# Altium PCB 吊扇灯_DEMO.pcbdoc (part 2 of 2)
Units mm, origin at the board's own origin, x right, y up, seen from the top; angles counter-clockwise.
Board outline 117.71 x 71.75 mm, 2 copper layers (Top Layer, Bottom Layer); 71 components, 50 nets, 203 pads, 259 vias.
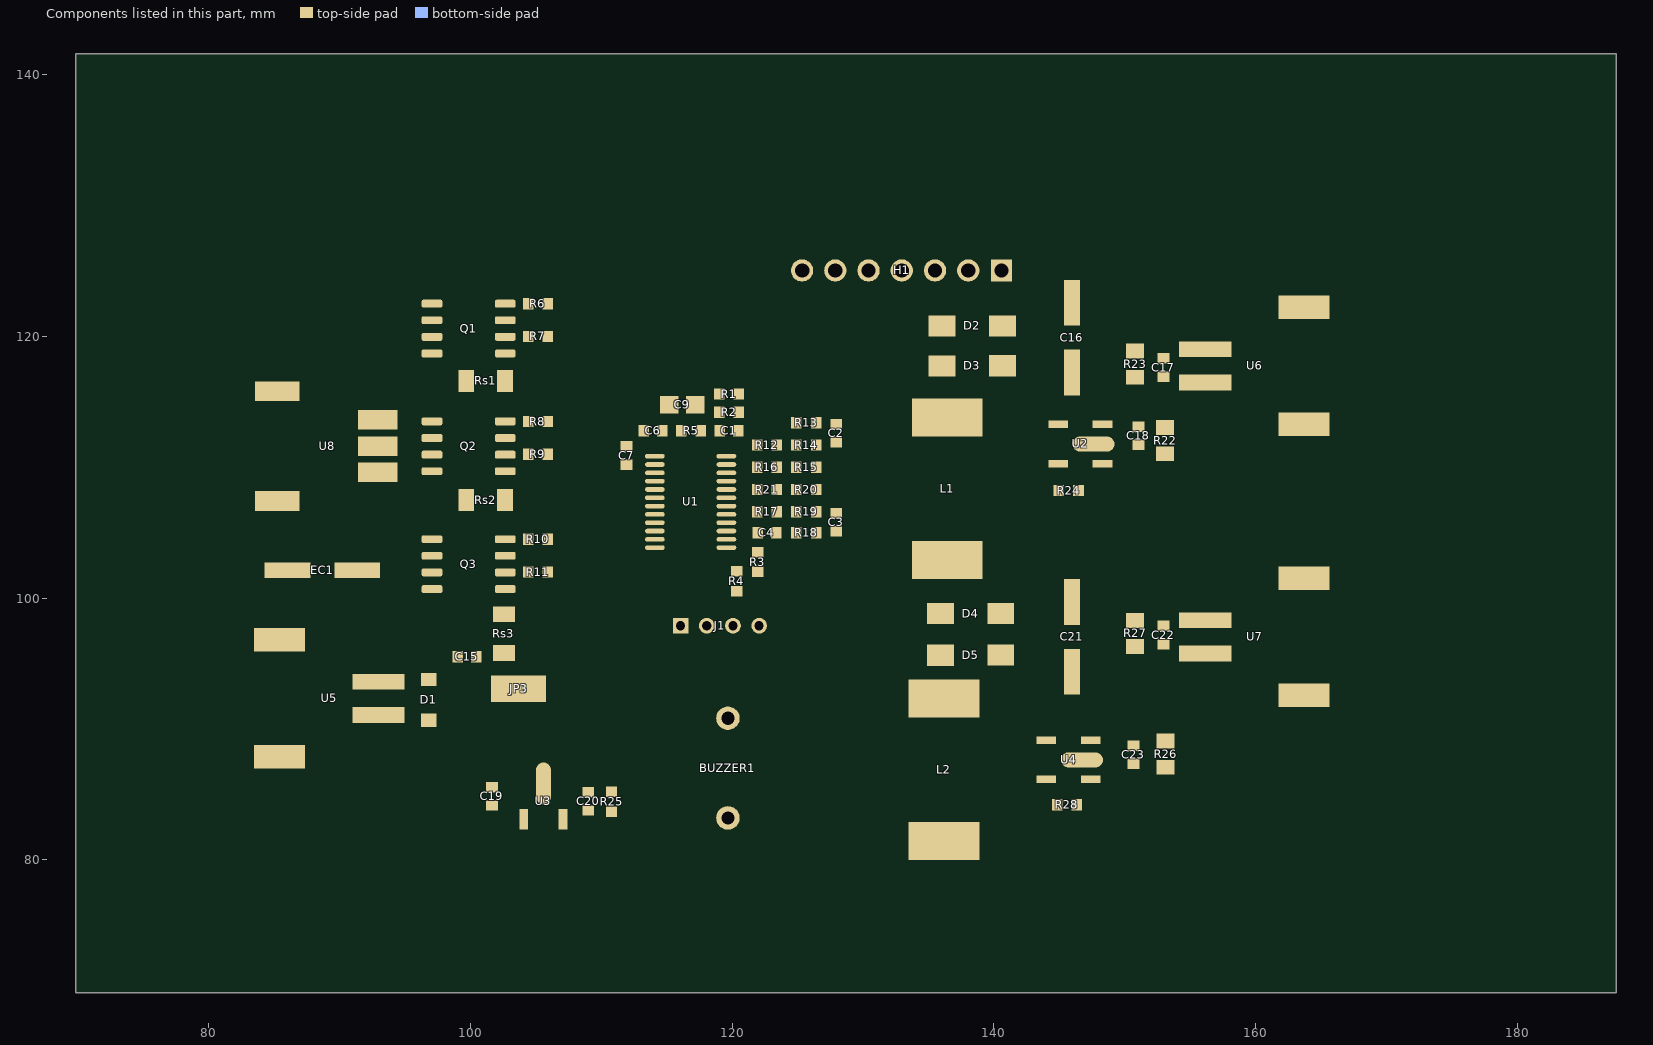
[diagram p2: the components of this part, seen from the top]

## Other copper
Top Layer:
  region net IBUS+: 98.37,117.401 98.77,117.801 99.97,117.801 100.27,117.501 100.27,101.801 101.07,101.001 103.77,101.001 104.07,100.701 104.07,98.001 103.97,97.901 100.27,97.901 100.17,98.001 100.17,98.901 98.37,100.701
  region net IS1+: 101.77,118.901 101.97,119.101 103.37,119.101 103.57,118.901 103.57,115.701 103.37,115.501 102.27,115.501 102.07,115.701 102.07,116.201 102.07,118.201 101.77,118.501
  region net IS1+: 101.77,118.901 101.97,119.101 103.37,119.101 103.57,118.901 103.57,115.701 103.37,115.501 102.27,115.501 102.07,115.701 102.07,116.201 102.07,118.201 101.77,118.501
  region net IS2+: 101.77,109.901 101.97,110.101 103.37,110.101 103.57,109.901 103.57,106.701 103.37,106.501 102.27,106.501 102.07,106.701 102.07,107.201 102.07,109.201 101.77,109.501
  region net 24V: 104.07,103.701 104.17,103.601 104.17,102.901 104.07,102.801 101.67,102.801 101.57,102.701 101.57,102.001 101.37,101.801 100.77,101.801 100.57,102.001 100.57,104.401 100.77,104.601 101.37,104.601 101.57,104.401 101.57,103.801 101.67,103.701
  region net 24V: 104.07,121.701 104.17,121.601 104.17,120.901 104.07,120.801 101.67,120.801 101.57,120.701 101.57,120.001 101.37,119.801 100.77,119.801 100.57,120.001 100.57,122.401 100.77,122.601 101.37,122.601 101.57,122.401 101.57,121.801 101.67,121.701
  region net 24V: 104.07,112.701 104.17,112.601 104.17,111.901 104.07,111.801 101.67,111.801 101.57,111.701 101.57,111.001 101.37,110.801 100.77,110.801 100.57,111.001 100.57,113.401 100.77,113.601 101.37,113.601 101.57,113.401 101.57,112.801 101.67,112.701
  region net +5V: 118.19,83.444 118.916,83.944 119.005,83.949 119.085,83.963 119.16,83.983 119.232,84.007 119.378,84.059 119.458,84.082 119.546,84.099 118.82,82.961 118.804,83.006 118.783,83.051 118.758,83.095 118.728,83.138 118.656,83.22 118.573,83.293 118.481,83.355 118.433,83.381 118.385,83.403 118.335,83.42 118.286,83.433 118.238,83.441
  region net +5V: 120.91,83.36 120.91,83.06 120.841,83.057 120.781,83.048 120.73,83.034 120.686,83.015 120.648,82.991 120.615,82.963 120.585,82.932 120.558,82.896 120.506,82.817 120.448,82.728 120.376,82.633 120.332,82.584 120.28,82.535 120.28,83.885 120.332,83.836 120.376,83.787 120.448,83.692 120.506,83.604 120.558,83.524 120.585,83.489 120.615,83.457 120.648,83.429 120.686,83.405 120.73,83.386 120.781,83.372 120.841,83.363
  region net BEE: 119.812,89.605 119.558,89.605 119.555,89.677 119.545,89.738 119.531,89.791 119.511,89.835 119.486,89.872 119.457,89.905 119.423,89.933 119.387,89.959 119.211,90.064 119.162,90.097 119.112,90.136 119.061,90.182 119.01,90.235 120.36,90.235 120.308,90.182 120.258,90.136 120.207,90.097 120.159,90.064 119.983,89.959 119.946,89.933 119.913,89.905 119.884,89.872 119.859,89.835 119.839,89.791 119.824,89.738 119.815,89.677
  region net BEE: 118.46,90.704 118.46,90.958 118.531,90.961 118.593,90.97 118.645,90.985 118.689,91.005 118.727,91.029 118.759,91.059 118.787,91.092 118.813,91.129 118.918,91.304 118.951,91.353 118.99,91.403 119.036,91.454 119.09,91.506 119.09,90.156 119.036,90.207 118.99,90.258 118.951,90.308 118.918,90.357 118.813,90.532 118.787,90.569 118.759,90.602 118.727,90.632 118.689,90.656 118.645,90.676 118.593,90.691 118.531,90.7
  region net AD_UDC: 118.755,112.245 118.564,112.337 ccw(c118.139,112.655) 118.67,112.655 119.073,112.351 ccw(c119.073,111.821)
  region net AD_UDC: 118.87,113.551 119.07,113.551 ccw(c119.445,113.551) 119.22,113.251 118.72,113.251 ccw(c118.495,113.551)
  region net IS1-: 127.22,113.306 127.22,113.506 ccw(c127.22,113.881) 127.52,113.656 127.52,113.156 ccw(c127.22,112.931)
  region net IS1-: 128.526,112.992 128.434,112.8 ccw(c128.116,112.376) 128.116,112.906 128.42,113.31 ccw(c128.95,113.31)
  region net IS1+: 127.22,111.706 127.22,111.906 ccw(c127.22,112.281) 127.52,112.056 127.52,111.556 ccw(c127.22,111.331)
  region net IS1+: 128.434,112.412 128.526,112.221 ccw(c128.95,111.903) 128.42,111.903 128.116,112.306 ccw(c128.116,112.837)
  region net IS2-: 127.22,104.906 127.22,105.106 ccw(c127.22,105.481) 127.52,105.256 127.52,104.756 ccw(c127.22,104.531)
  region net IS2-: 128.434,105.612 128.526,105.421 ccw(c128.95,105.103) 128.42,105.103 128.116,105.506 ccw(c128.116,106.037)
  region net IS2+: 127.22,106.506 127.22,106.706 ccw(c127.22,107.081) 127.52,106.856 127.52,106.356 ccw(c127.22,106.131)
  region net IS2+: 128.526,106.192 128.434,106 ccw(c128.116,105.576) 128.116,106.106 128.42,106.51 ccw(c128.95,106.51)
  region net ICOMP_P: 121.412,105.318 121.353,105.659 ccw(c126.615,110.921) 121.57,105.451 121.57,105.051 ccw(c120.97,104.876)
  region net ICOMP_P: 121.97,104.251 121.77,104.251 ccw(c121.395,104.251) 121.62,104.551 122.12,104.551 ccw(c122.345,104.251)
  region net $1N32: 114.945,111.901 114.595,111.901 ccw(c114.078,111.901) 114.332,112.351 115.07,112.351 ccw(c115.817,111.901)
  region net $1N32: 115.595,112.976 115.595,112.626 ccw(c115.595,111.97) 115.07,112.364 115.07,113.239 ccw(c115.595,113.633)
  region net 5VA: 111.07,109.951 111.07,110.251 ccw(c111.07,110.752) 111.488,110.476 111.488,109.796 ccw(c111.07,109.31)
  region net 5VA: 112.838,110.366 112.838,110.066 ccw(c112.838,109.504) 112.388,109.841 112.388,110.591 ccw(c112.838,110.929)
  region net 24V: 117.92,115.776 118.212,115.219 ccw(c119.485,114.265) 117.894,114.265 116.965,115.457 ccw(c116.965,117.048)
  region net 24V: 117.87,113.207 117.27,113.207 ccw(c116.145,113.207) 116.82,114.107 117.894,114.107 ccw(c134.758,113.207)
  region net 24V: 102.851,85.811 102.851,85.311 ccw(c102.851,83.361) 102.101,85.161 102.101,85.961 ccw(c102.851,87.761)
  region net 24V: 101.979,86.244 102.383,85.94 ccw(c103.316,85.161) 102.101,85.161 101.201,85.961 ccw(c101.201,87.177)
  region net +5V: 108.688,83.098 108.285,83.402 ccw(c107.351,84.18) 108.567,84.18 109.467,83.38 ccw(c109.467,82.165)
  region net +5V: 110.217,84.03 110.217,83.53 ccw(c110.217,81.58) 109.467,83.38 109.467,84.18 ccw(c110.217,85.98)
  region net GND: 122.753,97.43 122.541,97.218 122.483,97.267 122.426,97.297 122.369,97.311 122.312,97.315 122.185,97.306 122.113,97.301 122.032,97.303 122.669,97.939 122.67,97.859 122.665,97.786 122.656,97.66 122.66,97.602 122.675,97.545 122.704,97.488
  region net GND: 121.598,97.218 121.386,97.43 121.435,97.488 121.465,97.545 121.48,97.602 121.483,97.66 121.474,97.786 121.47,97.859 121.471,97.939 122.107,97.303 122.027,97.301 121.955,97.306 121.828,97.315 121.77,97.311 121.714,97.297 121.657,97.267
  region net GND: 122.541,98.585 122.753,98.373 122.704,98.314 122.675,98.258 122.66,98.201 122.656,98.143 122.665,98.016 122.67,97.944 122.669,97.864 122.032,98.5 122.113,98.501 122.185,98.497 122.312,98.488 122.369,98.492 122.426,98.506 122.483,98.536
  region net GND: 121.386,98.373 121.598,98.585 121.657,98.536 121.714,98.506 121.77,98.492 121.828,98.488 121.955,98.497 122.027,98.501 122.107,98.5 121.471,97.864 121.47,97.944 121.474,98.016 121.483,98.143 121.48,98.201 121.465,98.258 121.435,98.314
  region net SWDCLK: 119.421,98.408 119.563,98.55 119.597,98.519 119.629,98.495 119.66,98.477 119.69,98.465 119.719,98.459 119.748,98.456 119.806,98.461 119.937,98.489 120.016,98.499 120.107,98.5 119.471,97.864 119.472,97.955 119.483,98.034 119.51,98.165 119.515,98.223 119.513,98.252 119.506,98.281 119.494,98.311 119.477,98.342 119.453,98.374
  region net SWDIO: 118.577,98.55 118.718,98.408 118.687,98.374 118.663,98.342 118.645,98.311 118.634,98.281 118.627,98.252 118.625,98.223 118.629,98.165 118.657,98.034 118.668,97.955 118.669,97.864 118.032,98.5 118.124,98.499 118.202,98.489 118.333,98.461 118.392,98.456 118.421,98.459 118.45,98.465 118.48,98.477 118.51,98.495 118.543,98.519
  region net 5VA: 116.617,98.66 116.829,98.448 ccw(c117.465,97.971) 116.67,97.971 116.139,98.501 ccw(c116.139,99.297)
  region net $1N1115: 104.22,120.271 104.22,119.671 103.32,119.671 103.32,120.271
  region net $1N1124: 104.22,122.811 104.22,122.211 103.32,122.211 103.32,122.811
  region net $1N1118: 104.22,111.271 104.22,110.671 103.32,110.671 103.32,111.271
  region net $1N1122: 104.22,113.811 104.22,113.211 103.32,113.211 103.32,113.811
  region net AD_UDC: 120.173,115.063 120.014,115.187 ccw(c119.59,115.505) 120.12,115.505 120.491,115.169 ccw(c120.491,114.639)
  region net 24V: 118.17,115.301 118.17,115.901 ccw(c118.17,116.712) 118.613,116.033 118.613,115.169 ccw(c118.17,114.491)
  region net 24V: 118.72,116.933 119.32,116.933 ccw(c123.425,116.933) 119.42,116.033 118.613,116.033 ccw(c114.867,116.933)
  region net AD_UDC: 119.366,114.739 119.526,114.616 ccw(c119.95,114.298) 119.42,114.298 119.048,114.633 ccw(c119.048,115.164)
  region net AD_UDC: 119.07,113.469 118.87,113.469 ccw(c118.495,113.469) 118.72,113.769 119.22,113.769 ccw(c119.445,113.469)
  region net IBUS+: 122.784,102.142 122.784,101.888 ccw(c122.784,101.412) 122.403,101.698 122.403,102.333 ccw(c122.784,102.618)
  region net ICOMP_P: 121.77,104.225 121.97,104.225 ccw(c122.345,104.225) 122.12,103.925 121.62,103.925 ccw(c121.395,104.225)
  region net LED2_PWM: 119.832,102.498 120.049,102.564 ccw(c120.367,102.988) 120.367,102.458 119.938,102.18 ccw(c119.407,102.18)
  region net LED2_PWM: 120.937,101.668 120.728,101.517 ccw(c120.324,100.978) 120.324,101.652 120.802,102.072 ccw(c121.475,102.072)
  region net $1N32: 115.188,112.626 115.188,112.976 ccw(c115.188,113.641) 115.713,113.233 115.713,112.369 ccw(c115.188,111.962)
  region net 24V: 117.27,114.133 117.87,114.133 ccw(c120.534,114.133) 118.026,113.233 117.22,113.233 ccw(c109.125,114.133)
  region net 24V: 117.464,111.977 116.981,112.131 ccw(c116.027,112.847) 117.22,112.847 118.026,112.369 ccw(c118.843,110.598)
  region net $1N1124: 103.113,122.211 103.113,122.811 ccw(c103.113,126.192) 104.013,122.933 104.013,122.069 ccw(c103.113,119.288)
  region net HOU: 106.851,122.676 106.851,122.326 ccw(c106.851,121.662) 106.326,122.069 106.326,122.933 ccw(c106.851,123.341)
  region net $1N1115: 103.113,119.671 103.113,120.271 ccw(c103.113,122.852) 104.013,120.433 104.013,119.569 ccw(c103.113,115.65)
  region net LOU: 106.851,120.176 106.851,119.826 ccw(c106.851,119.162) 106.326,119.569 106.326,120.433 ccw(c106.851,120.841)
  region net $1N1122: 103.113,113.211 103.113,113.811 ccw(c103.113,117.192) 104.013,113.933 104.013,113.069 ccw(c103.113,110.288)
  region net HOV: 106.851,113.676 106.851,113.326 ccw(c106.851,112.662) 106.326,113.069 106.326,113.933 ccw(c106.851,114.341)
  region net $1N1118: 103.113,110.671 103.113,111.271 ccw(c103.113,113.852) 104.013,111.433 104.013,110.569 ccw(c103.113,106.65)
  region net LOV: 106.512,110.707 106.34,110.384 ccw(c105.783,109.641) 105.783,110.569 106.326,111.264 ccw(c107.254,111.264)
  region net $1N1123: 103.113,104.211 103.113,104.811 ccw(c103.113,108.192) 104.013,104.933 104.013,104.069 ccw(c103.113,101.288)
  region net HOW: 106.851,104.676 106.851,104.326 ccw(c106.851,103.662) 106.326,104.069 106.326,104.933 ccw(c106.851,105.341)
  region net $1N1121: 103.113,101.671 103.113,102.271 ccw(c103.113,104.852) 104.013,102.433 104.013,101.569 ccw(c103.113,97.65)
  region net LOW: 106.851,102.176 106.851,101.826 ccw(c106.851,101.162) 106.326,101.569 106.326,102.433 ccw(c106.851,102.841)
  region net OP2-: 123.073,111.168 122.914,111.292 ccw(c122.49,111.61) 123.02,111.61 123.391,111.274 ccw(c123.391,110.744)
  region net OP2-: 123.618,112.296 123.997,112.392 ccw(c124.559,111.83) 123.826,112.138 123.352,112.138 ccw(c123.177,112.738)
  region net IS1-: 127.126,113.506 127.126,113.306 ccw(c127.126,112.931) 126.826,113.156 126.826,113.656 ccw(c127.126,113.881)
  region net OP2-: 124.473,112.868 124.407,113.085 ccw(c123.983,113.403) 124.513,113.403 124.791,112.974 ccw(c124.791,112.444)
  region net IS1+: 127.126,111.906 127.126,111.706 ccw(c127.126,111.331) 126.826,111.556 126.826,112.056 ccw(c127.126,112.281)
  region net OP2+: 124.97,110.974 124.77,110.974 ccw(c124.395,110.974) 124.62,111.274 125.12,111.274 ccw(c125.345,110.974)
  region net OP2+: 124.77,110.738 124.97,110.738 ccw(c125.345,110.738) 125.12,110.438 124.62,110.438 ccw(c124.395,110.738)
  region net OP2+: 121.516,109.511 121.407,109.685 ccw(c120.983,110.003) 121.513,110.003 121.791,109.574 ccw(c121.791,108.945)
  region net OP2+: 122.266,110.544 122.426,110.421 ccw(c122.85,110.103) 122.32,110.103 121.948,110.438 ccw(c121.948,110.969)
  region net 5VA: 123.62,109.156 123.32,109.156 ccw(c122.819,109.156) 123.095,109.574 123.826,109.574 ccw(c124.146,109.156)
  region net OP1-: 122.794,106.906 122.794,107.106 ccw(c123.02,107.448) 123.02,107.038 123.02,106.756 ccw(c122.794,106.661)
  region net OP1-: 123.932,106.185 123.766,106.068 ccw(c123.448,105.644) 123.448,106.174 123.826,106.503 ccw(c124.357,106.503)
  region net IS2-: 127.126,105.106 127.126,104.906 ccw(c127.126,104.531) 126.826,104.756 126.826,105.256 ccw(c127.126,105.481)
  region net OP1-: 124.407,105.428 124.573,105.544 ccw(c124.891,105.969) 124.891,105.438 124.513,105.109 ccw(c123.983,105.109)
  region net IS2+: 127.126,106.706 127.126,106.506 ccw(c127.126,106.131) 126.826,106.356 126.826,106.856 ccw(c127.126,107.081)
  region net OP1+: 124.77,107.338 124.97,107.338 ccw(c125.345,107.338) 125.12,107.038 124.62,107.038 ccw(c124.395,107.338)
  region net OP1+: 124.97,107.574 124.77,107.574 ccw(c124.395,107.574) 124.62,107.874 125.12,107.874 ccw(c125.345,107.574)
  region net OP1+: 121.407,108.628 121.473,108.844 ccw(c121.791,109.269) 121.791,108.738 121.513,108.309 ccw(c120.983,108.309)
  region net OP1+: 122.426,107.892 122.266,107.768 ccw(c121.948,107.344) 121.948,107.874 122.32,108.21 ccw(c122.85,108.21)
  region net 5VA: 123.32,109.156 123.62,109.156 ccw(c124.146,109.156) 123.826,108.738 123.095,108.738 ccw(c122.819,109.156)
  region net LED_PWM: 144.182,108.102 144.182,108.356 ccw(c144.182,108.833) 144.563,108.547 144.563,107.912 ccw(c144.182,107.626)
  region net $1N4328: 146.355,109.042 146.609,109.042 ccw(c147.085,109.042) 146.799,108.661 146.164,108.661 ccw(c145.879,109.042)
  region net +5V: 109.613,83.53 109.613,84.03 ccw(c109.613,88.268) 110.363,84.097 110.363,83.291 ccw(c109.613,82.237)
  region net +5V: 111.977,83.944 111.977,83.444 ccw(c111.977,81.532) 111.227,83.291 111.227,84.097 ccw(c111.977,85.856)
  region net BEE: 111.608,85.328 111.608,85.074 ccw(c111.608,84.598) 111.227,84.883 111.227,85.518 ccw(c111.608,85.804)
  region net LED2_PWM: 144.055,84.099 144.055,84.353 ccw(c144.055,84.83) 144.436,84.544 144.436,83.909 ccw(c144.055,83.623)
  region net $2N531: 145.808,84.585 145.959,84.793 ccw(c146.363,85.332) 146.363,84.658 145.943,84.181 ccw(c145.269,84.181)
  region net IBUS+: 100.595,116.701 100.595,116.501 ccw(c100.595,116.126) 100.295,116.351 100.295,116.851 ccw(c100.595,117.076)
  region net IS1+: 101.87,116.501 101.87,116.701 ccw(c101.87,116.879) 102.045,116.851 102.045,116.351 ccw(c101.87,116.324)
  region net IS2+: 101.745,107.401 101.745,107.601 ccw(c101.745,107.976) 102.045,107.751 102.045,107.251 ccw(c101.745,107.026)
  region net IBUS+: 103.801,98.907 103.801,98.653 ccw(c103.801,98.177) 103.42,98.463 103.42,99.098 ccw(c103.801,99.383)
  region net BEE: 114.227,103.308 113.973,103.308 113.97,103.447 113.963,103.512 113.949,103.57 113.926,103.618 113.911,103.639 113.893,103.656 113.871,103.67 113.845,103.68 113.816,103.686 113.782,103.689 114.417,103.689 114.384,103.686 114.355,103.68 114.329,103.67 114.307,103.656 114.289,103.639 114.273,103.618 114.251,103.57 114.237,103.512 114.23,103.447
  region net OUT1: 115.056,104.628 115.056,104.374 114.986,104.372 114.919,104.366 114.803,104.349 114.675,104.324 114.675,104.679 114.803,104.654 114.919,104.636 114.986,104.631
  region net LOW: 113,104.961 113,105.311 113.525,105.314 113.525,104.959
  region net HOW: 113,105.596 113,105.946 113.525,105.949 113.525,105.594
  region net LOV: 113,106.231 113,106.581 113.525,106.584 113.525,106.229
  region net HOV: 113,106.866 113,107.216 113.525,107.219 113.525,106.864
  region net LOU: 113,107.501 113,107.851 113.525,107.854 113.525,107.499
  region net HOU: 113,108.136 113,108.486 113.525,108.489 113.525,108.134
  region net $1N32: 115.17,109.756 115.17,109.406 114.675,109.404 114.675,109.759
  region net 5VA: 113.075,110.066 113.075,110.366 113.237,110.371 113.375,110.38 113.525,110.394 113.525,110.039 113.375,110.053 113.237,110.062
  region net OP2O: 120.445,110.951 120.445,110.751 120.39,110.748 120.338,110.739 120.248,110.713 120.181,110.686 120.145,110.674 120.145,111.029 120.181,111.017 120.248,110.99 120.338,110.964 120.39,110.955
  region net OP2-: 120.445,110.316 120.445,110.116 120.39,110.113 120.338,110.104 120.248,110.078 120.181,110.051 120.145,110.039 120.145,110.394 120.181,110.382 120.248,110.355 120.338,110.329 120.39,110.32
  region net OP2+: 120.445,109.681 120.445,109.481 120.39,109.478 120.338,109.469 120.248,109.443 120.181,109.416 120.145,109.404 120.145,109.759 120.181,109.747 120.248,109.72 120.338,109.694 120.39,109.685
  region net OP1+: 120.445,109.046 120.445,108.846 120.39,108.843 120.338,108.834 120.248,108.808 120.181,108.781 120.145,108.769 120.145,109.124 120.181,109.112 120.248,109.085 120.338,109.059 120.39,109.05
  region net OP1-: 120.445,108.411 120.445,108.211 120.393,108.208 120.354,108.199 120.322,108.187 120.295,108.173 120.267,108.158 120.235,108.146 120.196,108.137 120.145,108.134 120.145,108.489 120.196,108.486 120.235,108.477 120.267,108.465 120.295,108.45 120.322,108.436 120.354,108.424 120.393,108.415
  region net OP1O: 120.4,107.776 120.4,107.576 120.356,107.573 120.322,107.564 120.296,107.552 120.272,107.538 120.249,107.523 120.222,107.511 120.188,107.502 120.145,107.499 120.145,107.854 120.188,107.851 120.222,107.842 120.249,107.83 120.272,107.815 120.296,107.801 120.322,107.789 120.356,107.78
  region net AD_UDC: 118.695,106.941 118.695,107.141 118.75,107.145 118.802,107.154 118.892,107.18 118.959,107.207 118.995,107.219 118.995,106.864 118.959,106.876 118.892,106.902 118.802,106.929 118.75,106.938
  region net ICOMP_P: 120.445,106.506 120.445,106.306 120.39,106.303 120.338,106.294 120.248,106.267 120.181,106.241 120.145,106.229 120.145,106.584 120.181,106.572 120.248,106.545 120.338,106.519 120.39,106.51
  region net LED_PWM: 120.416,105.898 120.416,105.644 120.366,105.642 120.32,105.636 120.239,105.619 120.179,105.602 120.145,105.594 120.145,105.949 120.179,105.941 120.239,105.924 120.32,105.906 120.366,105.901
  region net SWDIO: 118.695,105.036 118.695,105.236 118.75,105.24 118.802,105.249 118.892,105.275 118.959,105.302 118.995,105.314 118.995,104.959 118.959,104.971 118.892,104.997 118.802,105.024 118.75,105.033
  region net SWDCLK: 118.695,104.401 118.695,104.601 118.75,104.605 118.802,104.614 118.892,104.64 118.959,104.667 118.995,104.679 118.995,104.324 118.959,104.336 118.892,104.362 118.802,104.389 118.75,104.398
  region net LED2_PWM: 119.67,103.389 119.47,103.389 119.467,103.499 119.462,103.549 119.451,103.595 119.433,103.633 119.407,103.663 119.389,103.674 119.369,103.682 119.32,103.689 119.82,103.689 119.77,103.682 119.75,103.674 119.733,103.663 119.706,103.633 119.689,103.595 119.678,103.549 119.672,103.499
  region net $1N4328: 145.796,110.111 145.684,109.864 ccw(c145.28,109.325) 145.28,109.998 145.661,110.515 ccw(c146.335,110.515)
  region net +5V: 108.174,83.374 108.174,82.874 ccw(c108.174,81.937) 107.424,82.499 107.424,83.749 ccw(c108.174,84.312)
  region net $2N531: 144.907,85.845 144.659,85.734 ccw(c144.255,85.195) 144.255,85.868 144.772,86.249 ccw(c145.446,86.249)
  region net OUT1: 134.761,124.155 134.62,124.297 134.644,124.327 134.662,124.364 134.676,124.407 134.685,124.454 134.693,124.56 134.689,124.675 134.669,124.907 134.661,125.011 134.661,125.097 135.562,124.196 135.475,124.196 135.372,124.204 135.14,124.225 135.024,124.228 134.919,124.22 134.871,124.211 134.829,124.198 134.792,124.179
  region net +5V: 138.199,124.181 137.899,124.181 137.895,124.213 137.883,124.241 137.864,124.265 137.84,124.286 137.81,124.304 137.777,124.32 137.701,124.349 137.619,124.374 137.539,124.402 137.467,124.437 137.437,124.458 137.412,124.482 138.686,124.482 138.661,124.458 138.631,124.437 138.559,124.402 138.479,124.374 138.397,124.349 138.321,124.32 138.288,124.304 138.258,124.286 138.234,124.265 138.215,124.241 138.203,124.213
  region net 24V: 103.888,85.311 103.888,85.811 ccw(c103.888,86.749) 104.638,86.186 104.638,85.811 104.638,85.311 104.638,84.936 ccw(c103.888,84.374)
  region net 5VA: 123.62,108.68 123.32,108.68 123.317,108.712 123.31,108.745 123.285,108.81 123.249,108.872 123.207,108.925 123.732,108.925 123.691,108.872 123.655,108.81 123.629,108.745 123.622,108.712
  region net 5VA: 123.32,109.633 123.62,109.633 123.622,109.601 123.629,109.568 123.655,109.502 123.691,109.441 123.732,109.388 123.207,109.388 123.249,109.441 123.285,109.502 123.31,109.568 123.317,109.601
  region net IS1+: 105.904,115.794 105.762,115.935 105.789,115.967 105.807,116 105.817,116.032 105.821,116.066 105.82,116.139 105.82,116.223 106.192,115.852 106.107,115.852 106.034,115.853 106.001,115.848 105.968,115.838 105.936,115.821
  region net IS1+: 109.646,117.901 109.646,117.701 109.604,117.698 109.569,117.687 109.539,117.671 109.512,117.651 109.461,117.599 109.401,117.539 109.401,118.064 109.461,118.004 109.512,117.952 109.539,117.931 109.569,117.915 109.604,117.905
  region net IS1+: 116.893,117.701 116.893,117.901 116.935,117.905 116.97,117.915 117.001,117.931 117.027,117.952 117.078,118.004 117.138,118.064 117.138,117.539 117.078,117.599 117.027,117.651 117.001,117.671 116.97,117.687 116.935,117.698
  region net IS1+: 120.546,117.901 120.546,117.701 120.504,117.698 120.469,117.687 120.439,117.671 120.412,117.651 120.361,117.599 120.301,117.539 120.301,118.064 120.361,118.004 120.412,117.952 120.439,117.931 120.469,117.915 120.504,117.905
  region net 24V: 100.77,122.621 101.37,122.621 101.372,122.544 101.378,122.471 101.395,122.342 101.42,122.201 100.72,122.201 100.745,122.342 100.762,122.471 100.768,122.544
  region net IS1-: 121.09,117.247 121.153,117.057 121.115,117.04 121.085,117.02 121.061,116.995 121.042,116.967 121.01,116.901 120.972,116.826 120.806,117.324 120.882,117.286 120.947,117.253 120.979,117.242 121.013,117.236 121.049,117.237
  region net IS1-: 117.493,116.901 117.493,117.101 117.535,117.105 117.57,117.115 117.601,117.131 117.627,117.152 117.678,117.204 117.738,117.264 117.738,116.739 117.678,116.799 117.627,116.851 117.601,116.871 117.57,116.887 117.535,116.898
  region net IS1-: 110.19,117.247 110.253,117.057 110.215,117.04 110.185,117.02 110.161,116.995 110.142,116.967 110.11,116.901 110.072,116.826 109.906,117.324 109.982,117.286 110.047,117.253 110.079,117.242 110.113,117.236 110.149,117.237
  region net IS1-: 105.893,115.101 105.893,115.301 105.935,115.305 105.97,115.315 106.001,115.331 106.027,115.352 106.078,115.404 106.138,115.464 106.138,114.939 106.078,114.999 106.027,115.051 106.001,115.071 105.97,115.087 105.935,115.098
  region net IS2+: 128.941,105.931 128.799,106.072 128.825,106.103 128.838,106.131 128.842,106.157 128.839,106.184 128.826,106.245 128.821,106.281 128.82,106.323 129.192,105.952 129.149,105.953 129.113,105.958 129.053,105.971 129.026,105.974 128.999,105.97 128.971,105.956
  region net IS2-: 128.799,105.531 128.941,105.672 128.971,105.647 128.999,105.633 129.026,105.629 129.053,105.632 129.113,105.645 129.149,105.65 129.192,105.651 128.82,105.279 128.821,105.322 128.826,105.358 128.839,105.418 128.842,105.445 128.838,105.472 128.825,105.5
  region net 5VA: 111.546,110.251 111.546,109.951 111.514,109.949 111.481,109.942 111.416,109.916 111.355,109.88 111.301,109.839 111.301,110.364 111.355,110.323 111.416,110.287 111.481,110.261 111.514,110.254
  region net 5VA: 117.42,108.68 117.12,108.68 117.117,108.712 117.11,108.745 117.085,108.81 117.049,108.872 117.007,108.925 117.532,108.925 117.491,108.872 117.455,108.81 117.429,108.745 117.422,108.712
  region net IS2-: 107.399,105.531 107.541,105.672 107.571,105.647 107.599,105.633 107.626,105.629 107.653,105.632 107.713,105.645 107.749,105.65 107.792,105.651 107.42,105.279 107.421,105.322 107.426,105.358 107.439,105.418 107.442,105.445 107.438,105.472 107.425,105.5
  region net IS2+: 107.541,105.931 107.399,106.072 107.425,106.103 107.438,106.131 107.442,106.157 107.439,106.184 107.426,106.245 107.421,106.281 107.42,106.323 107.792,105.952 107.749,105.952 107.713,105.958 107.653,105.971 107.626,105.974 107.599,105.97 107.571,105.956
  region net 24V: 102.841,86.603 102.341,86.603 102.343,86.682 102.343,86.753 102.339,86.787 102.33,86.819 102.314,86.851 102.291,86.883 102.891,86.883 102.867,86.851 102.852,86.819 102.842,86.787 102.838,86.753 102.838,86.682
  region net LED_PWM: 120.726,104.658 120.98,104.658 120.985,104.614 120.997,104.566 121.016,104.52 121.041,104.483 120.666,104.483 120.69,104.52 120.709,104.566 120.722,104.614
  region net LED_PWM: 125.146,103.735 124.966,103.556 124.932,103.584 124.889,103.609 124.843,103.628 124.8,103.636 125.065,103.902 125.074,103.859 125.093,103.813 125.118,103.77
  region net OUT1: 116.274,104.374 116.321,104.628 116.364,104.632 116.412,104.642 116.458,104.657 116.496,104.677 116.449,104.305 116.414,104.334 116.369,104.356 116.32,104.37
  region net OUT1: 126.083,104.202 126.083,104.002 126.059,104 126.035,103.994 125.989,103.975 125.947,103.947 125.908,103.914 125.908,104.289 125.947,104.257 125.989,104.229 126.035,104.209 126.059,104.204
  region net +5V: 129.563,97.272 129.263,97.272 129.263,97.32 129.261,97.366 129.25,97.408 129.24,97.428 129.225,97.447 129.601,97.447 129.586,97.428 129.576,97.408 129.565,97.366 129.563,97.32
  region net IBUS+: 113.589,101.641 113.335,101.641 113.33,101.685 113.318,101.733 113.299,101.779 113.274,101.816 113.649,101.816 113.625,101.779 113.606,101.733 113.593,101.685
  region net IBUS+: 123.173,101.888 123.186,102.142 123.23,102.146 123.278,102.158 123.324,102.176 123.361,102.2 123.348,101.825 123.312,101.85 123.266,101.87 123.218,101.883
  region net +5V: 130.99,109.336 131.29,109.566 131.284,109.505 131.277,109.451 131.279,109.43 131.286,109.412 131.302,109.399 131.328,109.391 131.043,109.161 131.043,109.191 131.037,109.214 131.019,109.248 130.999,109.282 130.993,109.306
  region net OP1+: 124.17,107.506 ccw(c124.17,108.506) 124.77,107.706 124.87,107.406 124.77,107.106 ccw(c124.17,106.306) 124.17,107.306
  region net OP2+: 124.17,110.906 ccw(c124.17,111.906) 124.77,111.106 124.87,110.806 124.77,110.506 ccw(c124.17,109.706) 124.17,110.706
Bottom Layer:
  region net 24V: 102.07,97.678 102.07,113.501 102.07,119.901 102.07,121.901 101.37,122.601 98.97,122.601 98.37,122.001 98.37,100.301 97.07,99.001 89.617,99.001 89.617,94.146 135.599,94.146 135.599,122.58 131.902,122.58 131.902,97.358 130.988,96.444 103.303,96.444
  region net GND: 121.386,98.373 121.598,98.585 121.657,98.536 121.714,98.506 121.77,98.492 121.828,98.488 121.955,98.497 122.027,98.501 122.107,98.5 121.471,97.864 121.47,97.944 121.474,98.016 121.483,98.143 121.48,98.201 121.465,98.258 121.435,98.314
  region net GND: 121.598,97.218 121.386,97.43 121.435,97.488 121.465,97.545 121.48,97.602 121.483,97.66 121.474,97.786 121.47,97.859 121.471,97.939 122.107,97.303 122.027,97.301 121.955,97.306 121.828,97.315 121.77,97.311 121.714,97.297 121.657,97.267
  region net GND: 122.541,98.585 122.753,98.373 122.704,98.314 122.675,98.258 122.66,98.201 122.656,98.143 122.665,98.016 122.67,97.944 122.669,97.864 122.032,98.5 122.113,98.501 122.185,98.497 122.312,98.488 122.369,98.492 122.426,98.506 122.483,98.536
  region net GND: 122.753,97.43 122.541,97.218 122.483,97.267 122.426,97.297 122.369,97.311 122.312,97.315 122.185,97.306 122.113,97.301 122.032,97.303 122.669,97.939 122.67,97.859 122.665,97.786 122.656,97.66 122.66,97.602 122.675,97.545 122.704,97.488
  region net 5VA: 122.993,109.006 122.993,109.306 123.026,109.309 123.058,109.316 123.124,109.342 123.185,109.378 123.238,109.419 123.238,108.894 123.185,108.935 123.124,108.971 123.058,108.997 123.026,109.004
  region net IS1+: 106.6,116.428 106.655,116.236 106.616,116.221 106.585,116.202 106.561,116.178 106.541,116.151 106.506,116.086 106.465,116.013 106.32,116.517 106.394,116.476 106.458,116.44 106.489,116.428 106.522,116.421 106.559,116.42
  region net IS1+: 108.925,117.38 108.777,117.514 108.802,117.548 108.818,117.581 108.826,117.614 108.829,117.648 108.824,117.721 108.82,117.805 109.21,117.454 109.126,117.449 109.053,117.446 109.019,117.44 108.987,117.428 108.956,117.409
  region net IS1+: 117.846,117.901 117.846,117.701 117.804,117.698 117.769,117.687 117.739,117.671 117.712,117.651 117.661,117.599 117.601,117.539 117.601,118.064 117.661,118.004 117.712,117.952 117.739,117.931 117.769,117.915 117.804,117.905
  region net IS1+: 119.593,117.701 119.593,117.901 119.635,117.905 119.67,117.915 119.701,117.931 119.727,117.952 119.778,118.004 119.838,118.064 119.838,117.539 119.778,117.599 119.727,117.651 119.701,117.671 119.67,117.687 119.635,117.698
  region net IS1-: 120.193,116.901 120.193,117.101 120.235,117.105 120.27,117.115 120.301,117.131 120.327,117.152 120.378,117.204 120.438,117.264 120.438,116.739 120.378,116.799 120.327,116.851 120.301,116.871 120.27,116.887 120.235,116.898
  region net IS1-: 118.446,117.101 118.446,116.901 118.404,116.898 118.369,116.887 118.339,116.871 118.312,116.851 118.261,116.799 118.201,116.739 118.201,117.264 118.261,117.204 118.312,117.152 118.339,117.131 118.369,117.115 118.404,117.105
  region net IS1-: 109.388,116.699 109.299,116.878 109.335,116.9 109.362,116.925 109.381,116.953 109.396,116.983 109.418,117.053 109.445,117.133 109.68,116.663 109.6,116.69 109.531,116.713 109.498,116.72 109.464,116.721 109.428,116.714
  region net IS1-: 106.691,115.567 106.811,115.407 106.78,115.379 106.758,115.35 106.743,115.319 106.734,115.286 106.725,115.214 106.713,115.13 106.398,115.55 106.481,115.538 106.553,115.528 106.587,115.527 106.621,115.532 106.655,115.545
  region net IS2+: 128.991,105.931 128.849,106.072 128.86,106.091 128.862,106.115 128.859,106.143 128.851,106.174 128.831,106.235 128.824,106.263 128.82,106.288 129.227,105.956 129.17,105.954 129.102,105.956 129.038,105.952 129.011,105.944
  region net IS2-: 128.799,105.531 128.941,105.672 128.971,105.647 128.999,105.633 129.026,105.629 129.053,105.632 129.113,105.645 129.149,105.65 129.192,105.651 128.82,105.279 128.821,105.322 128.826,105.358 128.839,105.418 128.842,105.445 128.838,105.472 128.825,105.5
  region net 5VA: 111.513,109.871 111.301,109.658 111.276,109.679 111.248,109.698 111.184,109.726 111.115,109.744 111.048,109.752 111.419,110.123 111.428,110.056 111.445,109.988 111.474,109.923 111.492,109.895
  region net 5VA: 116.793,109.006 116.793,109.306 116.826,109.309 116.858,109.316 116.924,109.342 116.985,109.378 117.038,109.419 117.038,108.894 116.985,108.935 116.924,108.971 116.858,108.997 116.826,109.004
  region net 5VA: 117.746,109.306 117.746,109.006 117.714,109.004 117.681,108.997 117.616,108.971 117.555,108.935 117.501,108.894 117.501,109.419 117.555,109.378 117.616,109.342 117.681,109.316 117.714,109.309
  region net IS2-: 107.999,105.672 108.141,105.531 108.115,105.5 108.102,105.472 108.098,105.445 108.1,105.418 108.113,105.358 108.119,105.322 108.119,105.279 107.748,105.651 107.79,105.65 107.827,105.645 107.887,105.632 107.914,105.629 107.94,105.633 107.968,105.647
  region net IS2+: 108.14,106.072 107.999,105.931 107.968,105.956 107.94,105.97 107.914,105.974 107.887,105.971 107.827,105.958 107.79,105.952 107.748,105.952 108.119,106.323 108.119,106.281 108.113,106.245 108.1,106.184 108.098,106.157 108.102,106.131 108.115,106.103
  region net 24V: 102.341,87.692 102.841,87.692 102.838,87.613 102.838,87.542 102.842,87.508 102.852,87.475 102.867,87.443 102.891,87.412 102.291,87.412 102.314,87.443 102.33,87.475 102.339,87.508 102.343,87.542 102.343,87.613
  region net LED_PWM: 121.194,104.445 121.194,104.191 121.149,104.186 121.101,104.174 121.055,104.155 121.019,104.13 121.019,104.505 121.055,104.481 121.101,104.462 121.149,104.449
  region net LED_PWM: 124.485,104.037 124.665,104.216 124.699,104.188 124.742,104.163 124.788,104.144 124.831,104.136 124.566,103.87 124.557,103.913 124.538,103.959 124.513,104.002
  region net OUT1: 116.977,104.597 116.977,104.343 116.933,104.339 116.885,104.326 116.839,104.307 116.802,104.283 116.802,104.658 116.839,104.633 116.885,104.614 116.933,104.602
  region net OUT1: 125.412,104.253 125.592,104.432 125.626,104.404 125.669,104.379 125.715,104.36 125.758,104.351 125.493,104.086 125.484,104.129 125.466,104.175 125.44,104.218
  region net +5V: 129.548,97.959 129.76,97.747 129.725,97.713 129.695,97.679 129.673,97.641 129.666,97.62 129.663,97.597 129.397,97.862 129.421,97.865 129.442,97.872 129.48,97.894 129.514,97.925
  region net IBUS+: 113.782,102.133 113.82,101.879 113.775,101.875 113.726,101.861 113.681,101.839 113.645,101.811 113.607,102.184 113.645,102.164 113.691,102.148 113.739,102.137
  region net IBUS+: 123.18,101.879 123.18,102.133 123.224,102.138 123.272,102.15 123.318,102.17 123.355,102.194 123.355,101.819 123.318,101.843 123.272,101.862 123.224,101.875
  region net +5V: 131.443,108.803 131.143,108.803 131.143,108.852 131.14,108.897 131.129,108.939 131.119,108.959 131.105,108.978 131.48,108.978 131.466,108.959 131.456,108.939 131.445,108.897 131.442,108.852
  region net 24V: 98.138,95.204 97.557,95.079 97.53,95.114 97.517,95.148 97.515,95.181 97.517,95.213 97.519,95.244 97.516,95.276 97.502,95.308 97.472,95.341 97.974,95.386 97.956,95.355 97.953,95.342 97.955,95.33 97.97,95.31 97.995,95.292 98.066,95.256 98.103,95.233

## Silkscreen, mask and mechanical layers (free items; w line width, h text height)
Top Silkscreen Layer:
  circle w0.254: c86.109,128.4 r3
  circle w0.254: c86.109,82.4 r3
  circle w0.254: c163.109,82.4 r3
  circle w0.254: c163.109,128.4 r3
  text "LED-" at 152.425,120.802 h2
  text "U" at 94.92,113.182 h1
  text "LED+" at 154.788,111.785 h2
  text "V" at 94.894,111.049 h1
  text "W" at 94.793,109.017 h1
  text "LED-" at 151.892,99.746 h2
  text "5V" at 116.47,94.501 h0.8 r90
  text "SDO" at 118.503,94.501 h0.8 r90
  text "SCK" at 120.536,94.501 h0.8 r90
  text "GND" at 122.57,94.501 h0.8 r90
  text "VCC" at 92.989,94.463 h0.8
  text "LED+" at 152.044,92.939 h2
  text "GND" at 93.218,89.306 h0.8
  text "20251209" at 90.195,83.388 h1.5
  text "吊扇灯_DEMO" at 89.687,80.137 h2.5
  text "V1_0" at 104.038,79.959 h2.5
Mechanical Layer:
  circle w0.025: c86.109,128.4 r1.6
  circle w0.025: c86.109,82.4 r1.6
  circle w0.025: c163.109,82.4 r1.6
  circle w0.025: c163.109,128.4 r1.6
  lines w0.254: 83.161,82.4 ccw(c86.161,82.4) 86.161,79.4 163.161,79.4 ccw(c163.161,82.4) 166.161,82.4 166.161,128.4 ccw(c163.161,128.4) 163.161,131.4 86.161,131.4 ccw(c86.161,128.4) 83.161,128.4 83.161,82.4
Mech6:
  text "H:1.6MM" at 170.713,81.382 h3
